
// ===== library types =====

// folder: SIKO GmbH/AP05

TYPE "DT_AP05_IOL_ABS_PDI"
   STRUCT
      bs08_Reserved : Bool;   // Used in DisplayMode
      bs09_IncrementalMeasurement : Bool;   // True if incremental measurement is active
      bs10_TargetValueState : Bool;   // True if target value is active
      bs11_BatteryState : Bool;   // True if battery state is critical or low
      bs12_SpeedError : Bool;   // True if max speed was exceeded
      bs13_KeyConfiguration : Bool;   // True if key is actuated
      bs14_KeyCalibration : Bool;   // True if key is actuated
      bs15_KeyIncremental : Bool;   // True if key is actuated
      bs00_IndicatorCW : Bool;   // True if indicator cw is on
      bs01_IndicatorCCW : Bool;   // True if indicator ccw is on
      bs02_CalibrationExecuted : Bool;   // True if calibration was executed by command via interface
      bs03_Reserved : Bool;   // Used in DisplayMode
      bs04_GuardingBit : Bool;   // Communication guarding
      bs05_TargetWindowReached : Bool;   // True if target window is reached
      bs06_Deviation : Bool;   // Deviation from actual value to target
      bs07_GeneralError : Bool;   // True if error occurred
      nReserved : Word;
      nActualValue : DInt;   // Absolute position value
   END_STRUCT;
END_TYPE

TYPE "DT_AP05_IOL_ABS_PDO"
   STRUCT
      bc08_Reserved : Bool;   // Used in DisplayMode
      bc09_TargetValueActive : Bool;   // If true TargetValue is active
      bc10_Reserved : Bool;
      bc11_LED1Green : Bool;   // If true LED is on. Function controlled via Parameter LEDMode
      bc12_LED1Red : Bool;   // see bc11
      bc13_LED2Green : Bool;   // see bc11
      bc14_LED2Red : Bool;   // see bc11
      bc15_LEDBlinking : Bool;   // If true LEDs are blinking when on
      bc00_CalibrationExecute : Bool;   // If true calibration becomes executed
      bc01_Reserved : Bool;
      bc02_Reserved : Bool;   // Used in DisplayMode
      bc03_DisplayRange : Bool;   // If true display range is extended
      bc04_GuardingBit : Bool;   // Communication guarding
      bc05_ErrorAck : Bool;   // If true the actual error is acknowledged
      bc06_Reserved : Bool;   // Used in DisplayMode
      bc07_Reserved : Bool;   // Used in DisplayMode
      nReserved : Word;
      nTargetValue : DInt;   // Absolute target value
   END_STRUCT;
END_TYPE

// folder: (top level)

FUNCTION_BLOCK "SIKO_IOL_PRM"   // FB501, SCL
TITLE = SIKO_IOL_PRM
{ S7_Optimized_Access := 'FALSE' }
AUTHOR : SIKO_ch
FAMILY : IO-Link-Devices
NAME : 0.01
VERSION : 0.01
// Acyclic parameter access via IO-Link
   VAR_INPUT
      bcReset : Bool;   // Reset function block
      DC_HwId : HW_IO;   // Hardware identification of the IOL master module (HW_IO) from HW configuration
      DC_Port : Int;   // Port/channel number on which the IO-Link device is operated. (ET200 = 0 .. 4)
      DC_CAP : DInt;   // Client Access Point (CAP), with ET200 always 227 dec
      bcExecute : Bool;   // Rising edge executes command
      bcReadWrite : Bool;   // Command type 0 = read / 1 write
      nIndex : Int;   // IO-Link index
      nSubindex : Int;   // IO-Link subindex
      nWriteValue : DInt;   // Value to write
      sWriteString : String [32];   // String to write
   END_VAR
   VAR_OUTPUT
      bsBusy : Bool;   // Function block status - busy
      bsError : Bool;   // Function block status - error
      bsDone : Bool;   // Function block status - done
      bsString : Bool;   // Function block status - resonse is a string
      nReadValue : DInt;   // Read value
      sReadString : String [32];   // Read string
      nStatus : DWord;   // DP/ PNIO - error status; ERROR flag = 1 - detailed communication error status
      nIolStatus : DWord;   // IO-Link error status; ERROR flag = 1 - detailed IO-Link error status
      nSmState : Int;   // Status of the function block internal state machine
   END_VAR
   VAR
      DC_DwordBuffer : DWord;
      varrByteBuffer AT DC_DwordBuffer : Array[0..3] of Byte;
      fbIoLinkDevice : "IO_LINK_DEVICE";
      varrRecordBuffer : Array[0..231] of Byte;
      vnDataLength : Int;
      vnForCounter : Int;
      vnBytesToWrite : Int;
      vnStatus : DWord;
      vnIolStatus : DWord;
      vbOsrExecute : Bool;
      vbMemExecute : Bool;
      vbWriteCommand : Bool;
      vbReadAfterWrite : Bool;
      vnSmState : Int;
      vbEnable : Bool;
      vbBusy : Bool;
      vbError : Bool;
      vbDone : Bool;
      vbReadWrite : Bool;
      vsWriteString : String [32];
      vstWriteString AT vsWriteString : Struct
         vnSize : USInt;
         vnLength : USInt;
         varrChar : Array[0..31] of Char;
      END_STRUCT;
   END_VAR
   VAR CONSTANT
      SM_IDLE : Int := 0;
      SM_START_READ_REQUEST : Int := 1;
      SM_CHECK_READ_RESPONSE : Int := 2;
      SM_FINISH_READ_CMD : Int := 3;
      SM_START_WRITE_REQUEST : Int := 4;
      SM_CHECK_WRITE_RESPONSE : Int := 5;
      SM_FINISH_WRITE_CMD : Int := 6;
   END_VAR
BEGIN
   ///////////////////////////////////////////////////////////////////////////////////////////////
   // Name: SIKO_IOL_PRM
   ///////////////////////////////////////////////////////////////////////////////////////////////
   // Version history
   ///////////////////////////////////////////////////////////////////////////////////////////////
   // Date        | Vers. | created               | Author          | Remark
   // dd.mm.yyyy  |       | with                  |                 | 
   // ---------------------------------------------------------------------------------
   // 09.07.2020  | 0.1.0  | TIA V14 SP1 Upd9      | SIKO GmbH / ch  | first test
   // 06.08.2020  | 0.2.0  | TIA V14 SP1 Upd9      | SIKO GmbH / ch  | support for index 2 access, new reset input
   // 07.08.2020  | 0.2.1  | TIA V14 SP1 Upd9      | SIKO GmbH / ch  | rising edge at bcExecute after reset necessary
   // 01.10.2020  | 1.0.0  | TIA V14 SP1 Upd9      | SIKO GmbH / ch  | first release
   ///////////////////////////////////////////////////////////////////////////////////////////////
   // Init
   IF #bcReset THEN
       // initialize outputs
       #bsDone := 0;
       #bsBusy := 0;
       #bsError := 0;
       #bsString := 0;
       #nStatus := 0;
       #nIolStatus := 0;
       #nReadValue := 0;
       #sReadString := '';

       // initialize internals
       #vbOsrExecute := FALSE;
       #vbWriteCommand := FALSE;
       #vbReadAfterWrite := FALSE;
       #vbEnable := FALSE;
       #vnSmState := #SM_IDLE;
   END_IF;

   ///////////////////////////////////////////////////////////////////////////////////////////////
   // new command on rising edge
   //
   IF #vbOsrExecute AND (#vnSmState = 0) AND NOT #bcReset THEN
       // set status outputs
       #bsDone := 0;
       #bsBusy := 1;
       #bsError := 0;
       #bsString := 0;
       #nStatus := 0;
       #nIolStatus := 0;

       #vbReadAfterWrite := FALSE;

       // always start with read request
       #vbReadWrite := FALSE;

       IF (#bcReadWrite) THEN
           // write command
           #vbWriteCommand := 1;
       ELSE
           // read command
           #vbWriteCommand := 0;
       END_IF;

       //always start with read request, except index 2
       IF (#nIndex = 2) AND (#vbWriteCommand) THEN
           //start with write request
           #vbReadWrite := 1;
           #vnDataLength := 1;
           #vnBytesToWrite := 1;
           #vnSmState := #SM_START_WRITE_REQUEST;
       ELSE
           //start with read request 
           #vnSmState := #SM_START_READ_REQUEST;
       END_IF;
   END_IF;

   CASE #vnSmState OF
       #SM_START_READ_REQUEST: // read request
           #vbEnable := TRUE;
           // clear input buffer
           #nReadValue := 0;
           #sReadString := '';
           #vnSmState := #SM_CHECK_READ_RESPONSE;
       #SM_CHECK_READ_RESPONSE: // check read response
           IF (#vbDone OR #vbError) AND NOT #vbBusy THEN
               #vbEnable := FALSE;
           END_IF;

           IF #vbDone AND NOT #vbBusy THEN
               IF #vnDataLength > 32 THEN
                   // set status outputs and error string
                   #bsDone := FALSE;
                   #bsBusy := FALSE;
                   #bsError := TRUE;
                   #bsString := TRUE;
                   #nStatus := #vnStatus;
                   #nIolStatus := #vnIolStatus;
                   #sReadString := 'ERROR_DATA_SIZE_TOO_LARGE';
                   #vnSmState := #SM_FINISH_READ_CMD;
               ELSE
                   // copy data from record to buffer 
                   FOR #vnForCounter := 0 TO 3 BY 1 DO
                       #varrByteBuffer[#vnForCounter] := #varrRecordBuffer[#vnForCounter];
                   END_FOR;

                   IF (#vbWriteCommand) AND NOT (#vbReadAfterWrite) THEN
                       #vnSmState := #SM_START_WRITE_REQUEST;
                       #vbReadWrite := TRUE;
                       #vnBytesToWrite := #vnDataLength;
                   ELSE

                       //  distinction between string and numeric values
                       CASE #nIndex OF
                           16, 17, 18, 19, 20, 21, 22, 23, 24, 25, 26, 95, 180:
                               #bsString := true;
                               Chars_TO_Strg(Chars := #varrRecordBuffer,
                                             pChars := 0,
                                             Cnt := INT_TO_UINT(#vnDataLength),
                                             Strg => #sReadString);
                               // if index is a string, output value 0
                               #nReadValue := 0;
                               // set status
                               #bsDone := TRUE;
                               #bsBusy := FALSE;
                               #bsError := FALSE;
                               #nStatus := #vnStatus;
                               #nIolStatus := #vnIolStatus;
                           ELSE
                               IF (#vnDataLength > 4) THEN
                                   // error, too much data for numeric value    
                                   // set status outputs and error string
                                   #bsDone := FALSE;
                                   #bsBusy := FALSE;
                                   #bsError := TRUE;
                                   #bsString := TRUE;
                                   #nStatus := #vnStatus;
                                   #nIolStatus := #vnIolStatus;
                                   #sReadString := 'ERROR_DATA_SIZE_TOO_LARGE';
                               ELSE    
                                   IF (#vnDataLength = 1) THEN
                                       #nReadValue := DWORD_TO_DINT(SHR(IN := #DC_DwordBuffer & 16#FF000000, N := 24));
                                       // check for negative sign
                                       IF #nReadValue.%X7 THEN
                                           #nReadValue := (#nReadValue OR 16#FFFFFF00);
                                       END_IF;
                                   ELSIF (#vnDataLength = 2) THEN
                                       #nReadValue := DWORD_TO_DINT(SHR(IN := #DC_DwordBuffer & 16#FFFF0000, N := 16));
                                       // check for negative sign
                                       IF #nReadValue.%X15 THEN
                                           #nReadValue := (#nReadValue OR 16#FFFF0000);
                                       END_IF;
                                   ELSIF (#vnDataLength = 4) THEN
                                       #nReadValue := DWORD_TO_DINT(#DC_DwordBuffer);
                                   END_IF;
                                   // if index is a numeric value, output empty string
                                   #bsString := FALSE;
                                   #sReadString := '';
                                   // set status
                                   #bsDone := TRUE;
                                   #bsBusy := FALSE;
                                   #bsError := FALSE;
                                   #nStatus := #vnStatus;
                                   #nIolStatus := #vnIolStatus;
                               END_IF;
                       END_CASE;

                       #vnSmState := #SM_FINISH_READ_CMD;
                   END_IF;
               END_IF;
           ELSIF #vbError AND NOT #vbBusy THEN
               // set status outputs
               #bsBusy := FALSE;
               #bsError := TRUE;
               #bsDone := FALSE;
               #nStatus := #vnStatus;
               #nIolStatus := #vnIolStatus;
               #vnSmState := #SM_FINISH_READ_CMD;
           END_IF;
       #SM_FINISH_READ_CMD: // finish read command
           #vnSmState := #SM_IDLE;
       #SM_START_WRITE_REQUEST:  // write request
           // clear buffer 
           FOR #vnForCounter := 0 TO 3 BY 1 DO
               #varrByteBuffer[#vnForCounter] := 0;
           END_FOR;

           //  distinction between string and numeric values
           CASE #nIndex OF
               16, 17, 18, 19, 20, 21, 22, 23, 24, 25, 26, 95, 180:
                   // copy input
                   #vsWriteString := #sWriteString;
                   #vnBytesToWrite := #vstWriteString.vnLength;
                   // copy data from string to record 
                   FOR #vnForCounter := 0 TO USINT_TO_INT(#vstWriteString.vnLength) BY 1 DO
                       #varrRecordBuffer[#vnForCounter] := #vstWriteString.varrChar[#vnForCounter];
                   END_FOR;
               ELSE // numeric values
                   IF (#vnBytesToWrite = 1) THEN
                       #DC_DwordBuffer := DINT_TO_DWORD(SHL(IN := #nWriteValue & 16#000000FF, N := 24));
                   ELSIF (#vnBytesToWrite = 2) THEN
                       #DC_DwordBuffer := DINT_TO_DWORD(SHL(IN := #nWriteValue & 16#0000FFFF, N := 16));
                   ELSIF (#vnBytesToWrite = 4) THEN
                       #DC_DwordBuffer := DINT_TO_DWORD(#nWriteValue);
                   END_IF;

                   // copy data from buffer to record 
                   FOR #vnForCounter := 0 TO 3 BY 1 DO
                       #varrRecordBuffer[#vnForCounter] := #varrByteBuffer[#vnForCounter];
                   END_FOR;
           END_CASE;

           #vbEnable := TRUE;
           #vnSmState := #SM_CHECK_WRITE_RESPONSE;
       #SM_CHECK_WRITE_RESPONSE: // check write response    
           IF #vbDone OR #vbError AND NOT #vbBusy THEN
               #vbEnable := FALSE;
               #vnSmState := #SM_FINISH_WRITE_CMD;
           END_IF;

           IF #vbDone AND NOT #vbBusy THEN
               // set status outputs
               // status still busy
               #nStatus := #vnStatus;
               #nIolStatus := #vnIolStatus;
               #vnSmState := #SM_FINISH_WRITE_CMD;
           END_IF;

           IF #vbError AND NOT #vbBusy THEN
               // set status
               #bsBusy := FALSE;
               #bsError := TRUE;
               #bsDone := FALSE;
               #nStatus := #vnStatus;
               #nIolStatus := #vnIolStatus;
               #vnSmState := #SM_IDLE;
           END_IF;
       #SM_FINISH_WRITE_CMD: // finish write cycle
           IF (#nIndex = 2) THEN
               #vnSmState := #SM_IDLE;
               // set status bits
               #nReadValue := 0;
               #bsBusy := FALSE;
               #bsError := FALSE;
               #bsDone := TRUE;
           ELSE
               // readback written parameter
               #vbReadAfterWrite := TRUE;
               #vbReadWrite := FALSE;
               #vnSmState := #SM_START_READ_REQUEST;
           END_IF;
   END_CASE;

   // bcExecute: rising edge
   #vbOsrExecute := #bcExecute AND NOT #vbMemExecute;
   #vbMemExecute := #bcExecute;

   // Call "IO_LINK_DEVICE"
   #fbIoLinkDevice(REQ:=#vbEnable,
                            ID:=#DC_HwId,
                            CAP:=#DC_CAP,
                            RD_WR:=#vbReadWrite,
                            "PORT":=#DC_Port,
                            IOL_INDEX:=#nIndex,
                            IOL_SUBINDEX:=#nSubindex,
                            LEN:=#vnBytesToWrite,
                            DONE_VALID=>#vbDone,
                            BUSY=>#vbBusy,
                            ERROR=>#vbError,
                            STATUS=>#vnStatus,
                            IOL_STATUS=>#vnIolStatus,
                            RD_LEN=>#vnDataLength,
                            RECORD_IOL_DATA:=#varrRecordBuffer);

    // output actual state machine state
   #nSmState := #vnSmState;
END_FUNCTION_BLOCK

// folder: S7-1200/1500/Lib/S7-1200/1500/Common

FUNCTION_BLOCK "IO_LINK_DEVICE"   // FB50001, SCL
TITLE = IO_LINK_DEVICE
{ S7_Optimized_Access := 'TRUE' }
AUTHOR : SUP_FA
FAMILY : IO-Link
VERSION : 3.0
// Function block to read and write acyclic data on devices with IO-Link used on SIMATIC S7 controllers. (former IO_LINK_CALL)
   VAR_INPUT
      REQ : Bool;   // request function / Request Function / Neuer Auftrag
      ID : HW_IO;   // hardware identifier of IO-Link master module (HW_IO) from hw-config / Hardwarekennung des IOL-Master Moduls (HW_IO) aus HW-Konfiguration
      CAP : DInt := DINT#0;   // Client Access Point (CAP), for ET200 always 227 decimal / Client Access Point (CAP), bei ET200 immer 227 dez
      RD_WR : Bool;   // read and write access on IO-Link device 0: read, 1: write / Lese und Schreibzugriff auf IO-Link Device 0: Lesen, 1: schreiben
      PORT : Int := INT#0;   // number of port on IO-Link master module (ET200SP = 0..4) / Port/ Kanalnummer an dem das IO-Link Device betrieben wird. (ET200 = 0 .. 4)
      IOL_INDEX : Int := INT#0;   // address parameter Index (IO-Link Device) 0..32767 IOL-D, 65535 port functions / Adressparameter Index (IO-Link Device) 0..32767 IOL-D, 65535 port functions
      IOL_SUBINDEX : Int := INT#0;   // address parameter Subindex (IO-Link Device) 0 full record; 1-255 single parameter / Adressparameter Subindex (IO-Link Device) 0 ges. Record; 1-255 einz. Parameter
      LEN : Int := INT#0;   // length of writing data (netto data) / Länge der zu schreibenden Daten (Nettodaten)
   END_VAR
   VAR_OUTPUT
      DONE_VALID : Bool;   // validity 0: data invalid ; 1: data valid / Gültigkeit 0: Daten nicht gültig; 1: Daten gültig
      BUSY : Bool;   // 0: request finish 1: request in progress / 0: Auftrag abgeschlossen 1: Auftrag in Bearbeitung
      ERROR : Bool;   // Error Flag = 0: no error; 1: function aborted with error / Fehler Flag 0: kein Fehler; 1: Abbruch der Funktion mit Fehler
      STATUS : DWord := DW#16#00000000;   // DP/ PNIO - error status ; ERROR Flag = 1 - communication error status in detail / DP/ PNIO - Fehlerstatus; ERROR Flag = 1 - detaillierter Kommunikationsfehlerstatus
      IOL_STATUS : DWord := DW#16#00000000;   // IO-Link error status; ERROR flag = 1: IO-Link error status in detail / IO-Link Fehlerstatus; ERROR Flag = 1 - detaillierte IO-Link Fehlerstatus
      RD_LEN : Int := INT#0;   // length of read data record (number of bytes) / Länge des gelesenen Datensatzes (Anzahl Bytes)
   END_VAR
   VAR_IN_OUT
      RECORD_IOL_DATA : Array[0..231] of Byte;   // data area for reading / writing data (max. 232 byte) / Datenbereich für LESEN / SCHREIBEN (max. 232 Byte)
   END_VAR
   VAR
      RDREC_Function : RDREC;   // system function "read data record" (former SFB52) / Funktion Datensatz lesen (ehemals SFB52)
      WRREC_Function : WRREC;   // system function "write data record" (former SFB53) / Funktion Datensatz schreiben (ehemals SFB53)
      TP_poll : TP_TIME;   // poll rate read data record / Pollzeit für "Datensatz lesen"
      TON_monitoring : TON_TIME;   // request monitoring time / Überwachungszeit für Aufträge
      rdrec : Struct   // internal structure for RDREC / interne Struktur für RDREC
         valid : Bool;   // Function performed
         busy : Bool;   // Function busy
         error : Bool;   // Error flag
         status : DWord;   // Function result/error message
         length : UInt;   // Length of the fetched data record
      END_STRUCT;
      wrrec : Struct   // internal structure for WRREC / interne Struktur für WRREC
         length : UInt;   // length of write data record
         done : Bool;   // Function performed
         busy : Bool;   // Function busy
         error : Bool;   // Error flag
         status : DWord;   // Function result/error message
      END_STRUCT;
      read : Struct   // data area for reading data / Datenbereich für Lesedaten
         header : Struct
            CALL : Struct   // header for read/write data record
               Extended_Function_Num : Byte := 16#8;   // extended function number (fix coded 08h)
               Port : Byte;   // variable port (user interface) 0...255
               FI_Index : Word := 16#FE4A;   // FI index (fix coded 65098)
            END_STRUCT;
            IOL : Struct   // header for IO-Link
               Control : Byte;   // RD_WR = 0 = read = Control:=0x03 / / RD_WR = 1 = write = Control:=0x02
               Index_HighByte : Byte;   // index of data record 0…32767 (high byte)
               Index_LowByte : Byte;   // index of data record 0…32767 (low byte)
               Subindex : Byte;   // subindex for data record 0...255
            END_STRUCT;
         END_STRUCT;
         data : Array[0..231] of Byte;
      END_STRUCT;
      write : Struct   // data area for writing data / Datenbereich für Schreibdaten
         header : Struct
            CALL : Struct   // header for read/write data record
               Extended_Function_Num : Byte := 16#8;   // extended function number (fix coded 08h)
               Port : Byte;   // variable port (user interface) 0...255
               FI_Index : Word := 16#FE4A;   // FI index (fix coded 65098)
            END_STRUCT;
            IOL : Struct   // header for IO-Link
               Control : Byte;   // RD_WR = 0 = read = Control:=0x03 / / RD_WR = 1 = write = Control:=0x02
               Index_HighByte : Byte;   // index of data record 0…32767 (high byte)
               Index_LowByte : Byte;   // index of data record 0…32767 (low byte)
               Subindex : Byte;   // subindex for data record 0...255
            END_STRUCT;
         END_STRUCT;
         data : Array[0..231] of Byte;
      END_STRUCT;
      sequencecontrol : Int := INT#0;   // number of sequence control
      typeofrequest : Int := INT#0;   // type of request (0=Read, 1=Write)
      R_TRIG_REQ : Bool;   // impulse start new request / Impuls für neuen Auftrag starten
      R_TRIG_REQ_old : Bool;   // old value of REQ (previous cycle) / Flankenmerker
      F_TRIG_poll : Bool;   // impulse poll read data record (response) / Impuls für Pollen "Datensatz lesen"
      F_TRIG_poll_old : Bool;   // old value of Poll (previous cycle) / Flankenmerker
   END_VAR
   VAR_TEMP
      retval : Int;   // function return value / Variable für Rückgabewerte von Funktionen
      tmpWORD : Word;   // data type WORD for temporarily use / Datentyp WORD zur temporären Verwendung
      tmpDWORD : DWord;   // data type DWORD for temporarily use / Datentyp DWORD zur temporären Verwendung
      tmpINT : Int;   // data type INT for temporarily use / Datentyp INT zur temporären Verwendung
      i : Int;   // run tag for counting loops / Laufvariable für for-Schleifen
   END_VAR
BEGIN
   (*---------------------------------------------------------------------------------------------------------------------
   SIEMENS AG
   ©Copyright 2015. All Rights Reserved.
   -----------------------------------------------------------------------------------------------------------------------
   Limitation of liability
   This software was developed with largest care. However, the author can not guarantee, that the software runs under
   each version of STEP7 on each PLC flawlessly.
   There is no warranty for the software, to the extent permitted by applicable law. The copyright holder provides the
   software "as is" without warranty of any kind, either expressed or implied, including, but not limited to, the implied
   warranties of merchantability and fitness for a particular purpose. The entire risk as to the quality and performance
   of the software is with you. Should the software prove defective, you assume the cost of all necessary servicing,
   repair or correction. In no event unless required by applicable law will the copyright holder be liable to you for
   damages, including any general, special, incidental or consequential damages arising out of the use or inability to
   use the software (including but not limited to loss of data or data being rendered inaccurate or losses sustained by
   you or third parties or a failure of the software to operate with any other programs), even if such holder or other
   party has been advised of the possibility of such damages.
   Permission to use or copy this software for any purpose is hereby granted without fee, provided the above notices are
   retained on all copies. Permission to modify the code and to distribute modified code is granted, provided the above
   notices are retained, and a notice that the code was modified is included with the above copyright notice.
   -----------------------------------------------------------------------------------------------------------------------
   Functionality provided by this source (short description):
   Function block IO_LINK_DEVICE - used to read and write of acyclic data records on devices with IO-Link.
   Note:
   To read data records, the IO-Link master modules needs to know which data record is required. Therefore it is necessary
   to send at first a request via write data record (only header of 8 byte). As response the IO-Link master module
   will send the required data record.

   Status:     Released (tested)
   File name:  IO_LINK_DEVICE
   System :    SIMATIC S7-1200/1500
   Version :   3.0
   -----------------------------------------------------------------------------------------------------------------------
   Script to be stored on level ... in project (mark appropriate levels with [x] below)
   [ ] External
   [ ] All levels possible
   [x] Project level
   [ ] Controller level
   [ ] Device level
   [ ] Subobject level
   -----------------------------------------------------------------------------------------------------------------------
   Restrictions, known limitations:
   The limitation of 240 byte is based on PROFIBUS DP protocol. With PROFINET IO there wouldn't no limit but because of 
   compatibility reason it wasn't changed.
     - header =   8 byte
     - data   = 232 byte
   -----------------------------------------------------------------------------------------------------------------------
   Requirements, prerequisites, External resources used: nothing
   -----------------------------------------------------------------------------------------------------------------------
   Change log table (latest change is at the bottom OF the list):
   Version Date Changes applied
   V2.0.0 <2013-09-30> First created with TIA Portal V12 SP1
   V2.1.0 <2014-03-14> Upgrade system function 'WRREC' from V1.0 to V1.1 and released for TIA Portal V13
   V3.0.0 <2015-02-28> Upgrade and released for TIA Portal V13 SP1 (without backup/restore master parameter)
   V3.0.2 <2015-07-07> Change of #IOL_INDEX and #Port lower boundry to 0
   ---------------------------------------------------------------------------------------------------------------------*)

   (*---------------------------------------------------------------------------------------------------------------------
   Description of programmed IO-Link error codes
   8000 = time out
   8001 = wrong port
   8002 = wrong index
   8003 = wrong subindex
   8005 = wrong length for write data record
   8006 = wrong length for read data record
   8052 = error during reading data record
   8053 = error during writing data record
   All other codes are coming from a higher level!
   ---------------------------------------------------------------------------------------------------------------------*)

   (*---------------------------------------------------------------------------------------------------------------------
               NEW REQUEST
   ---------------------------------------------------------------------------------------------------------------------*)
   // detection rising edge of "REQ"
   #R_TRIG_REQ := #REQ = TRUE AND #R_TRIG_REQ_old = FALSE;
   #R_TRIG_REQ_old := #REQ = TRUE;

   // start new request if not busy
   IF #R_TRIG_REQ = TRUE AND #sequencecontrol = 0 THEN
       // Freeze record ID and CAP
       #WRREC_Function.ID := #ID;
       #WRREC_Function.INDEX := #CAP;
       #RDREC_Function.ID := #ID;
       #RDREC_Function.INDEX := #CAP;

       // Initialize outputs
       #DONE_VALID := FALSE;
       #BUSY := TRUE;
       #ERROR := FALSE;
       #STATUS := DW#16#00000000;
       #IOL_STATUS := DW#16#00000000;
       #RD_LEN := INT#0;

       // Initialize data area
       #read.header.CALL.Port := B#16#0;
       #read.header.IOL.Index_LowByte := B#16#0;
       #read.header.IOL.Index_HighByte := B#16#0;
       #read.header.IOL.Subindex := B#16#0;
       #i := INT#0; // initialize loop counter      
       FOR #i := 0 TO 231 DO
           #write.data[#i] := B#16#0;
           #read.data[#i] := B#16#0;
       END_FOR;

   (*---------------------------------------------------------------------------------------------------------------------
       Setup IO-LINK Call needs a specific header
   ---------------------------------------------------------------------------------------------------------------------*)
   // setup CALL header
   #write.header.CALL.Extended_Function_Num := 16#08;  // extended function number (fix coded 08h)
   #write.header.CALL.Port := INT_TO_BYTE(#PORT);  // 1..63 = PORT number, 64..255=reserved
   #write.header.CALL.FI_Index := 65098;  // IOL-Header is following (fix coded 65098)

   // setup IOL header 
   // CONTROL = please see below at BODY
   // INDEX
   #write.header.IOL.Index_LowByte := INT_TO_BYTE(#IOL_INDEX);
   #tmpWORD := INT_TO_WORD(#IOL_INDEX);
   #tmpWORD := SHR(IN := #tmpWORD, N := 8);
   #write.header.IOL.Index_HighByte := WORD_TO_BYTE(#tmpWORD);
   // SUBINDEX
   #write.header.IOL.Subindex := INT_TO_BYTE(#IOL_SUBINDEX);

   // BODY (data max. 232 Byte, Array 0..231 of Byte) 
   IF #RD_WR = TRUE THEN
       // IO-Link write data record requested, copy data from "RECORD_IOL_DATA"
       #write.header.IOL.Control := B#16#02; // CONTROL B#16#02 = write data record
       #wrrec.length := INT_TO_UINT(#LEN) + UINT#8;  // data length header + data = IO-Link write data record
       #typeofrequest := 2; // write data record
       // copy IOL_RECORD_DATA in working area
       #i := INT#0;    // initialize loop counter 
       FOR #i := 0 TO #LEN - 1 DO
           #write.data[#i] := #RECORD_IOL_DATA[#i];
       END_FOR;
   ELSE
       // IO-Link read data record requested
       #write.header.IOL.Control := 16#03;  // CONTROL 16#03 = read data record
       #wrrec.length := UINT#8; // data length only header = IO-Link read data record
       #typeofrequest := 1; // read data record        
   END_IF;
   #sequencecontrol := 1;  // Start sequence
   ELSE
       ;
   END_IF;

   (*---------------------------------------------------------------------------------------------------------------------
               SEQUENCE CONTROL
   ---------------------------------------------------------------------------------------------------------------------*)
   CASE #sequencecontrol OF
       1:  // Check input parameter        
           IF #PORT < INT#0 OR #PORT > INT#63 THEN // PORT (Wrong port address = 0x8001)
               #ERROR := TRUE;
               #IOL_STATUS := DW#16#80010000;
               #sequencecontrol := 99; // aborting function with error
           ELSIF #IOL_INDEX < INT#0 OR #IOL_INDEX > INT#32767 THEN    // INDEX (Wrong index = 0x8002)
               #ERROR := TRUE;
               #IOL_STATUS := DW#16#80020000;
               #sequencecontrol := 99; // aborting function with error
           ELSIF #IOL_SUBINDEX < INT#0 OR #IOL_SUBINDEX > INT#255 THEN    // SUBINDEX (Wrong subindex = 0x8003)
               #ERROR := TRUE;
               #IOL_STATUS := DW#16#80030000;
               #sequencecontrol := 99; // aborting function with error
           ELSIF #typeofrequest = 2 AND (#LEN < 1 OR #LEN > 232) THEN  // LEN (wrong length for write data record = 0x8004)
               #ERROR := TRUE;
               #IOL_STATUS := DW#16#80050000;
               #sequencecontrol := 99; // aborting function with error
           ELSIF #typeofrequest = 1 AND (#LEN < 0 OR #LEN > 232) THEN  // LEN (wrong length for read data record = 0x8005)
               #ERROR := TRUE;
               #IOL_STATUS := DW#16#80060000;
               #sequencecontrol := 99; // aborting function with error
           ELSE    // all input parameter are right
               #sequencecontrol := 2;
           END_IF;

       2:  (*-------------------------------------------------------------------------------------------------------------
           WRREC = Write Data Record
           Note:
           To read data records, the IO-Link master modules needs to know which PORT is required. Therefore it is necessary
           to send at first a request via write data record (header, 8 byte). As response the IO-Link master module will 
           send the required data record.
           -------------------------------------------------------------------------------------------------------------*)
           #WRREC_Function(REQ := TRUE,
                           LEN := #wrrec.length,
                           DONE => #wrrec.done,
                           BUSY => #wrrec.busy,
                           ERROR => #wrrec.error,
                           STATUS => #wrrec.status,
                           RECORD := #write);
           // output status during write data record
           IF #wrrec.busy THEN
               #STATUS := #wrrec.status;
               #IOL_STATUS := DW#16#00020000;  // 0002 = writing in progress 
           ELSIF #wrrec.error THEN
               #tmpDWORD := #wrrec.status AND DW#16#00FFFF00;  // filter status
               IF #tmpDWORD = DW#16#0080C200 THEN    // if resource #BUSY (#STATUS=80C2), then ... 
                   #sequencecontrol := 3;  // ... repeat write data record
               ELSE
                   #ERROR := TRUE;
                   #STATUS := #wrrec.status;   // ... otherwise output error status of "WRREC"
                   #IOL_STATUS := DW#16#80530000;  // ... with note '8053' = error status of "WRREC"
                   #sequencecontrol := 99; // aborting function with error
               END_IF;
           ELSIF #wrrec.done = TRUE THEN   // wait for write data record finish without error
               #TP_poll(IN := TRUE,
                        PT := T#100ms);    // poll for response
               #sequencecontrol := 4;
           ELSE
               ;
           END_IF;

       3:  // repeat write data record because resource was busy
           #WRREC_Function(REQ := FALSE);
           #sequencecontrol := 2;

       4:  // wait and poll for response = Read Data Record (RDREC)
           #WRREC_Function(REQ := FALSE);
           #TP_poll(IN := TRUE,
                    PT := T#100ms);

           // if poll rate executed then start read data record (on falling edge)
           #F_TRIG_poll := #TP_poll.Q = FALSE AND #F_TRIG_poll_old = TRUE;
           #F_TRIG_poll_old := #TP_poll.Q = TRUE;

           // RDREC = Read Data Record
           #RDREC_Function(REQ := #F_TRIG_poll,
                           MLEN := UINT#0, // length = 0 = read all data which are available
                           VALID => #rdrec.valid,
                           BUSY => #rdrec.busy,
                           ERROR => #rdrec.error,
                           STATUS => #rdrec.status,
                           LEN => #rdrec.length,
                           RECORD := #read);
           // output status during read data record
           IF #rdrec.busy THEN
               #STATUS := #rdrec.status;
               #IOL_STATUS := DW#16#00030000; // 16#0003 = reading in progress
           ELSIF #rdrec.error = TRUE THEN
               #tmpDWORD := #rdrec.status AND DW#16#00FFFF00;  // filter status
               IF #tmpDWORD = DW#16#0080C200 THEN  // if resource busy (status=80C2), then ... 
                   #sequencecontrol := 5;  // ... repeat read data record / continue polling
               ELSE
                   #ERROR := TRUE;
                   #STATUS := #rdrec.status;   // ... otherwise output error code of "RDREC"
                   #IOL_STATUS := DW#16#80520000;  // ... with note '8052' = error status of "RDREC"
                   #sequencecontrol := 99; // aborting function with error
               END_IF;
           ELSIF #rdrec.valid THEN
               IF  // check the response wether it matches the request (compare PORT, INDEX and SUBINDEX)
                   (#write.header.CALL.Port <> #read.header.CALL.Port) OR
                   (#write.header.IOL.Index_HighByte <> #read.header.IOL.Index_HighByte) OR
                   (#write.header.IOL.Index_LowByte <> #read.header.IOL.Index_LowByte) OR
                   (#write.header.IOL.Subindex <> #read.header.IOL.Subindex)
               THEN    // read data record don't match the request
                   #ERROR := TRUE;
                   #STATUS := #rdrec.status;
                   #IOL_STATUS := DW#16#70000000;  // output status '7000', no consistent data
                   #sequencecontrol := 99; // aborting function with error
               ELSIF #read.header.IOL.Control = B#16#80 THEN   // check the response for IO-Link errors
                   // State 0x80 = IOL_CALL_RES PDU shows IO-Link error detect
                   #ERROR := TRUE;
                   #STATUS := DW#16#00000000;
                   #IOL_STATUS.%B3 := #read.data[0];   // IO-Link master error code
                   #IOL_STATUS.%B2 := #read.data[1];   // IO-Link master error code
                   #IOL_STATUS.%B1 := #read.data[2];  // IO-Link device error code
                   #IOL_STATUS.%B0 := #read.data[3];  // IO-Link device additional error code

                   #sequencecontrol := 99; // aborting function with error
               ELSE    // read data are valid = output
                   #DONE_VALID := TRUE;
                   #BUSY := FALSE;
                   #ERROR := FALSE;
                   #STATUS := DW#16#00000000;
                   #IOL_STATUS := DW#16#00000000;  // request finished

                   IF #typeofrequest = 1 THEN
                       #RD_LEN := UINT_TO_INT(#rdrec.length - UINT#8);  // device parameter cover header and data,
                       // only data will be output
                       #i := INT#0; // initialize loop counter
                       FOR #i := 0 TO UINT_TO_INT(#rdrec.length - UINT#8 - UINT#1) DO
                           #RECORD_IOL_DATA[#i] := #read.data[#i];
                       END_FOR;
                   ELSE
                       ;
                   END_IF;
                   #sequencecontrol := 98;
               END_IF;
           ELSE
               ;
           END_IF;

       5:  // poll again for response because resource was busy
           #TP_poll(IN := FALSE,
                    PT := T#100ms);
           #RDREC_Function(REQ := FALSE,
                           RECORD := #read);
           #sequencecontrol := 4;  // ... repeat read data record / continue polling   

       98: // request done successfully
           #TP_poll(IN := FALSE,
                    PT := T#100ms);
           #RDREC_Function(REQ := FALSE,
                           RECORD := #read);
           IF #REQ = FALSE THEN
               #DONE_VALID := FALSE;
               #BUSY := FALSE;
               #ERROR := FALSE;
               #RD_LEN := INT#0;
               #STATUS := DW#16#00000000;
               #IOL_STATUS := DW#16#00010000; // ready for new request
               #sequencecontrol := 0;
               #typeofrequest := 0;
           ELSE
               ;
           END_IF;

       99: // Function aborted with error
           #TP_poll(IN := FALSE,
                    PT := T#100ms);
           #WRREC_Function(REQ := FALSE);
           #RDREC_Function(REQ := FALSE,
                           RECORD := #read);
           #DONE_VALID := FALSE;
           #BUSY := FALSE;
           #RD_LEN := INT#0;
           #sequencecontrol := 0;
           #typeofrequest := 0;

       ELSE  // no relevant case, ready for new request
           #WRREC_Function(REQ := FALSE);
           #RDREC_Function(REQ := FALSE,
                           RECORD := #read);
           #TP_poll(IN := FALSE,
                    PT := T#100ms);
           #TON_monitoring(IN := FALSE,
                           PT := T#20s);
           #sequencecontrol := 0;
           #typeofrequest := 0;
   END_CASE;

   (*---------------------------------------------------------------------------------------------------------------------
               MONITORING
   ---------------------------------------------------------------------------------------------------------------------*)
   #TON_monitoring(IN := #sequencecontrol > 0 AND #sequencecontrol < 98,
                   PT := T#20s);
   IF #TON_monitoring.Q THEN
       #ERROR := TRUE;
       #IOL_STATUS := DW#16#80000000; // request time out       
       #sequencecontrol := 99; // aborting function with error
   END_IF;
END_FUNCTION_BLOCK

// ===== library: CodeBlockByCopyVersionObject "None" =====

// ===== library: MasterCopy "SIKO_AP05_IOL_ABS" =====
